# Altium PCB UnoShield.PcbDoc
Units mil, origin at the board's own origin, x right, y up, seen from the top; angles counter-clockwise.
Board outline 2700 x 2100 mil, 4 copper layers (Top Layer, Signal Layer 1, Signal Layer 2, Bottom Layer), stack 30.634 mil thick; 52 components, 29 nets, 160 pads, 29 vias.
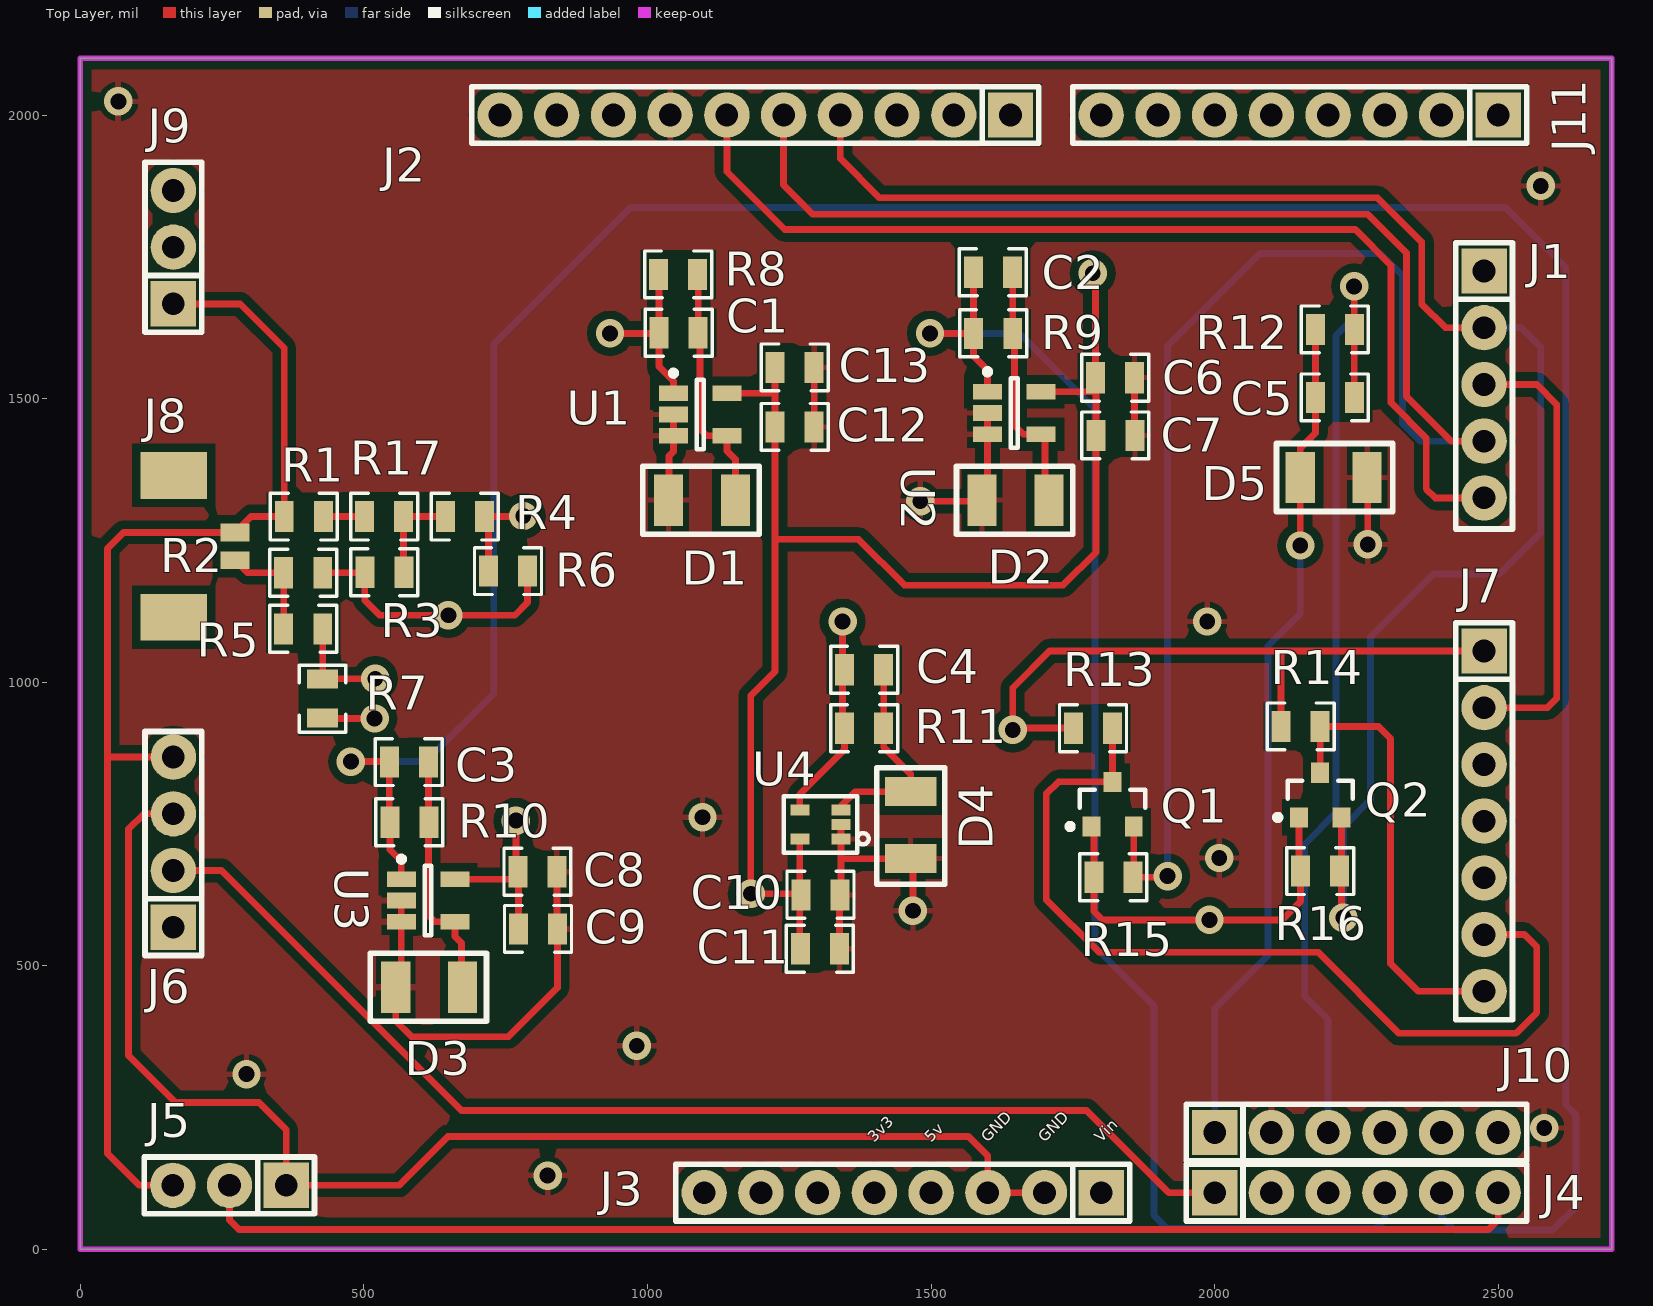
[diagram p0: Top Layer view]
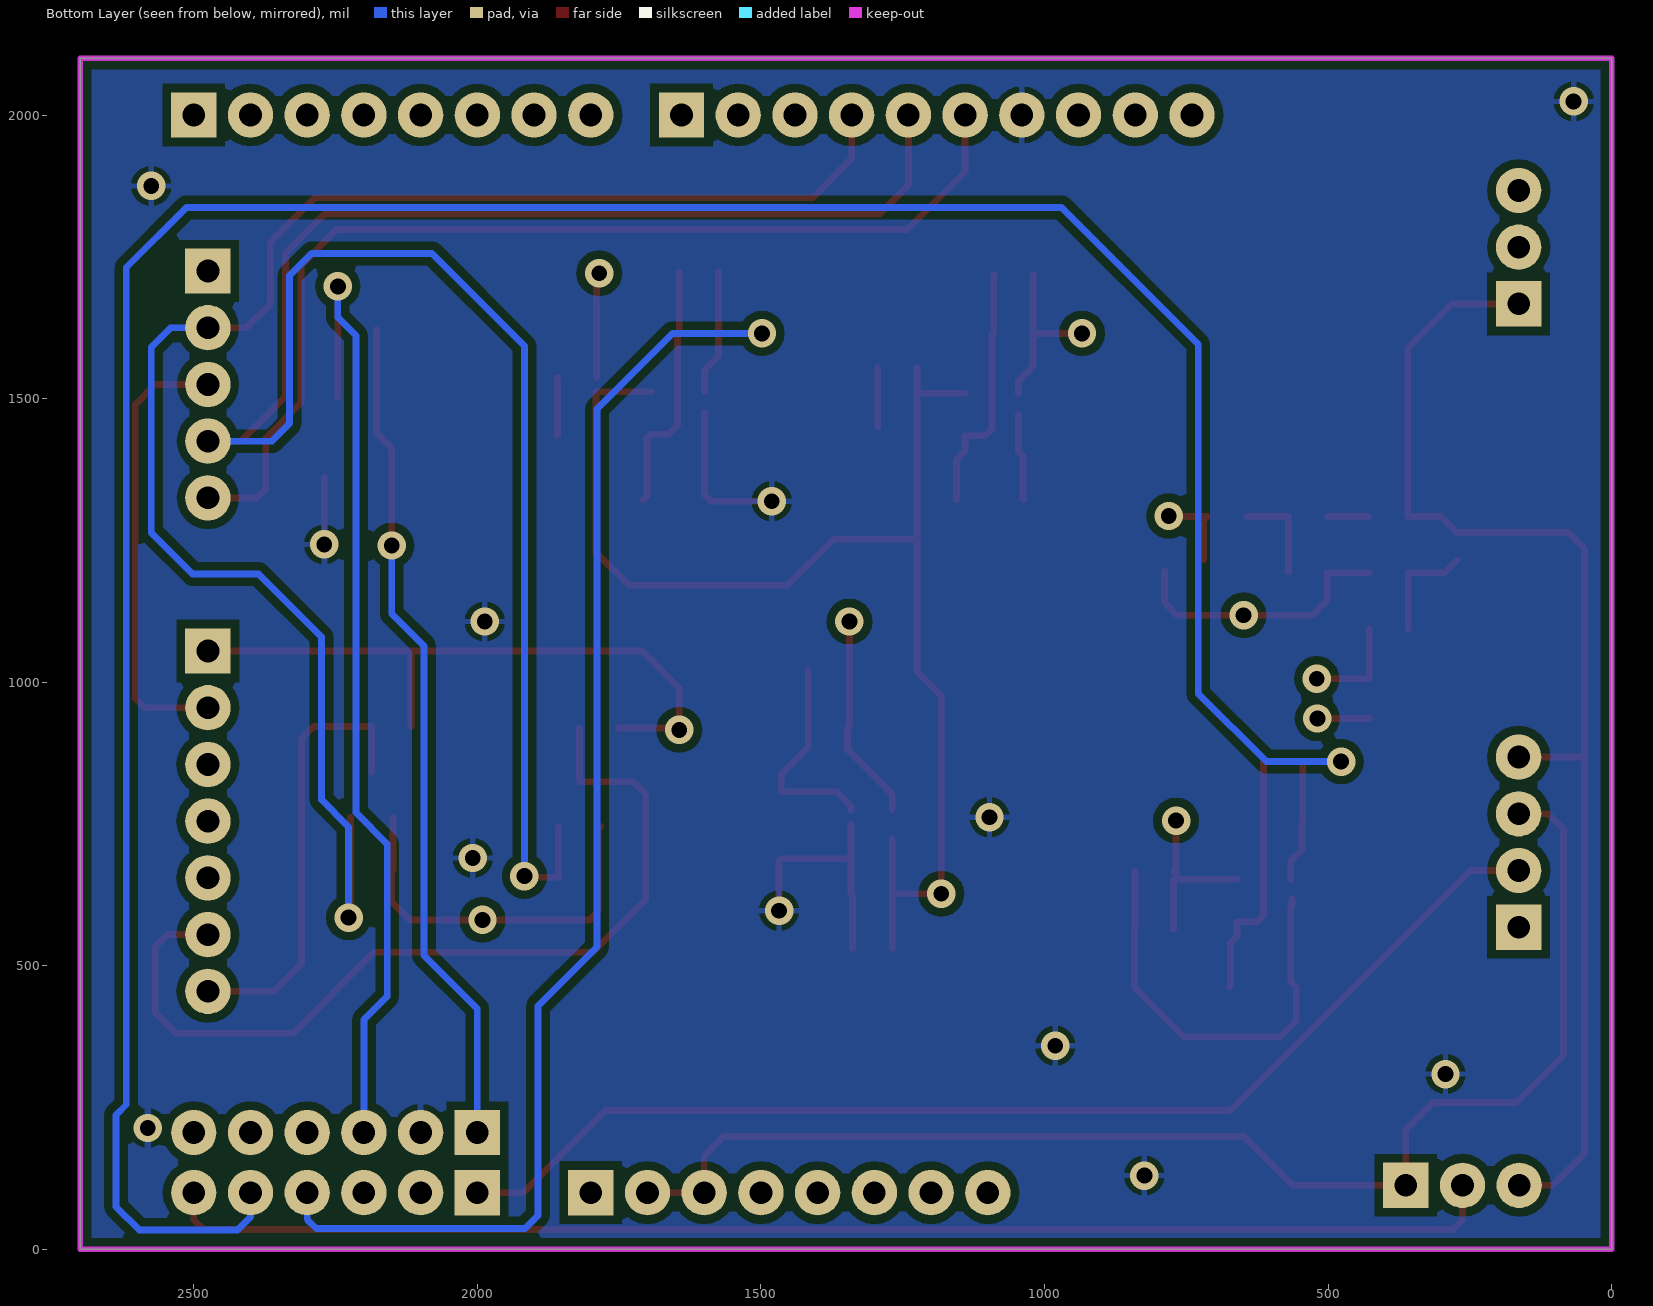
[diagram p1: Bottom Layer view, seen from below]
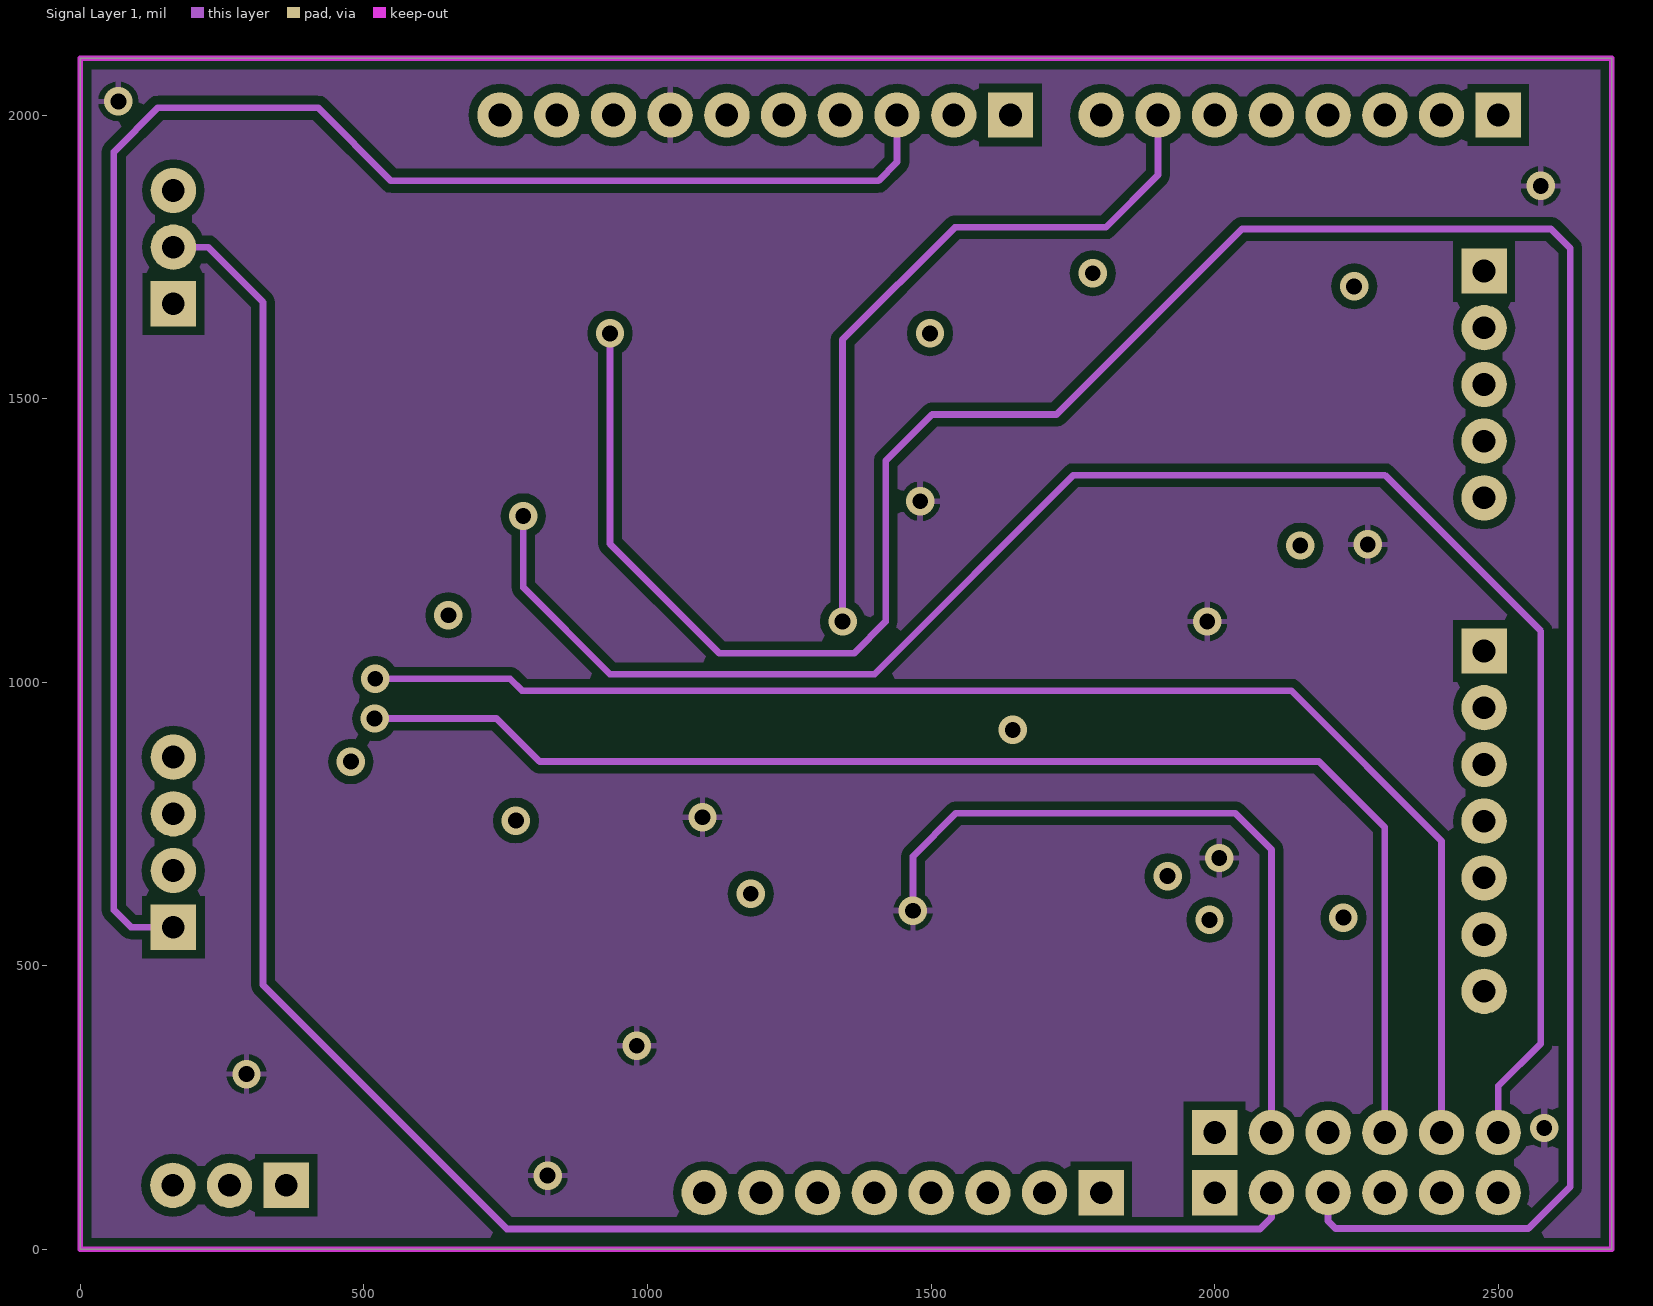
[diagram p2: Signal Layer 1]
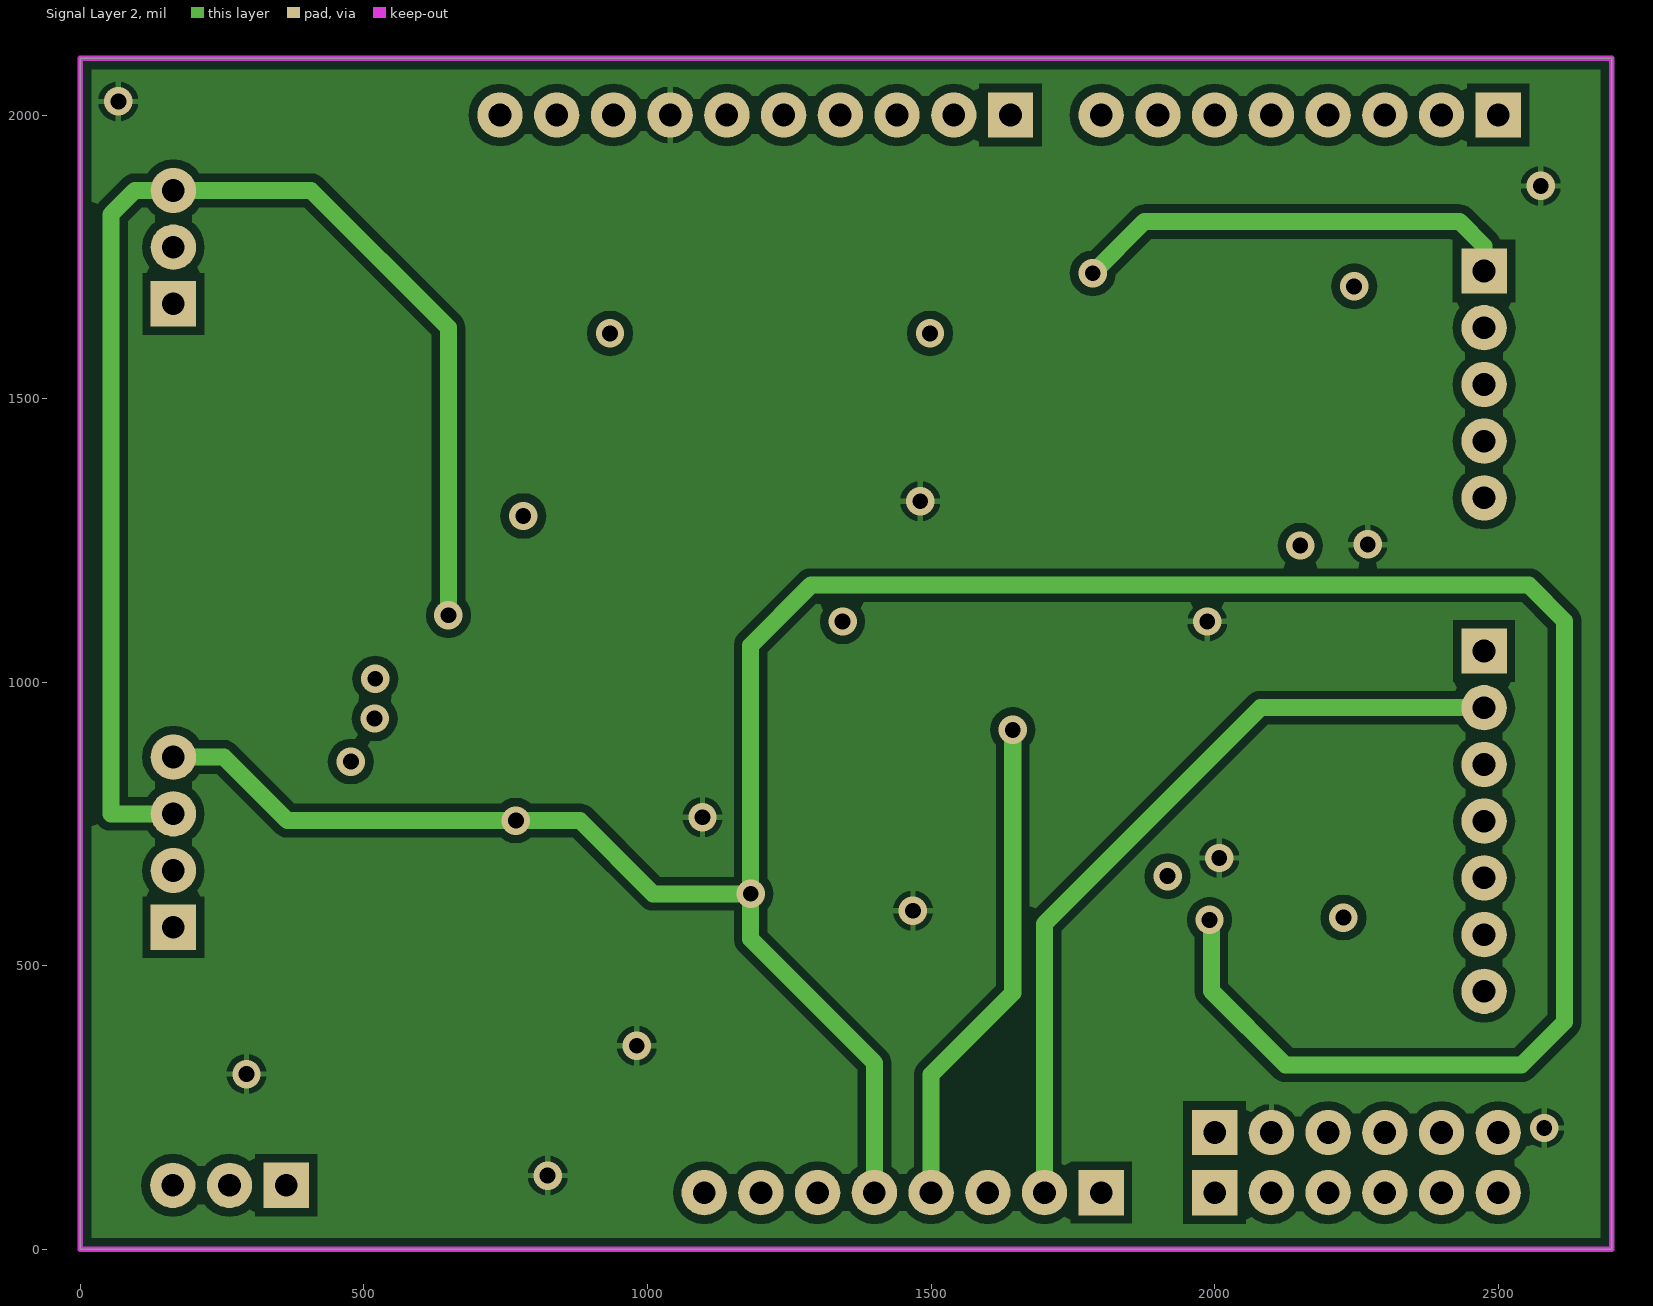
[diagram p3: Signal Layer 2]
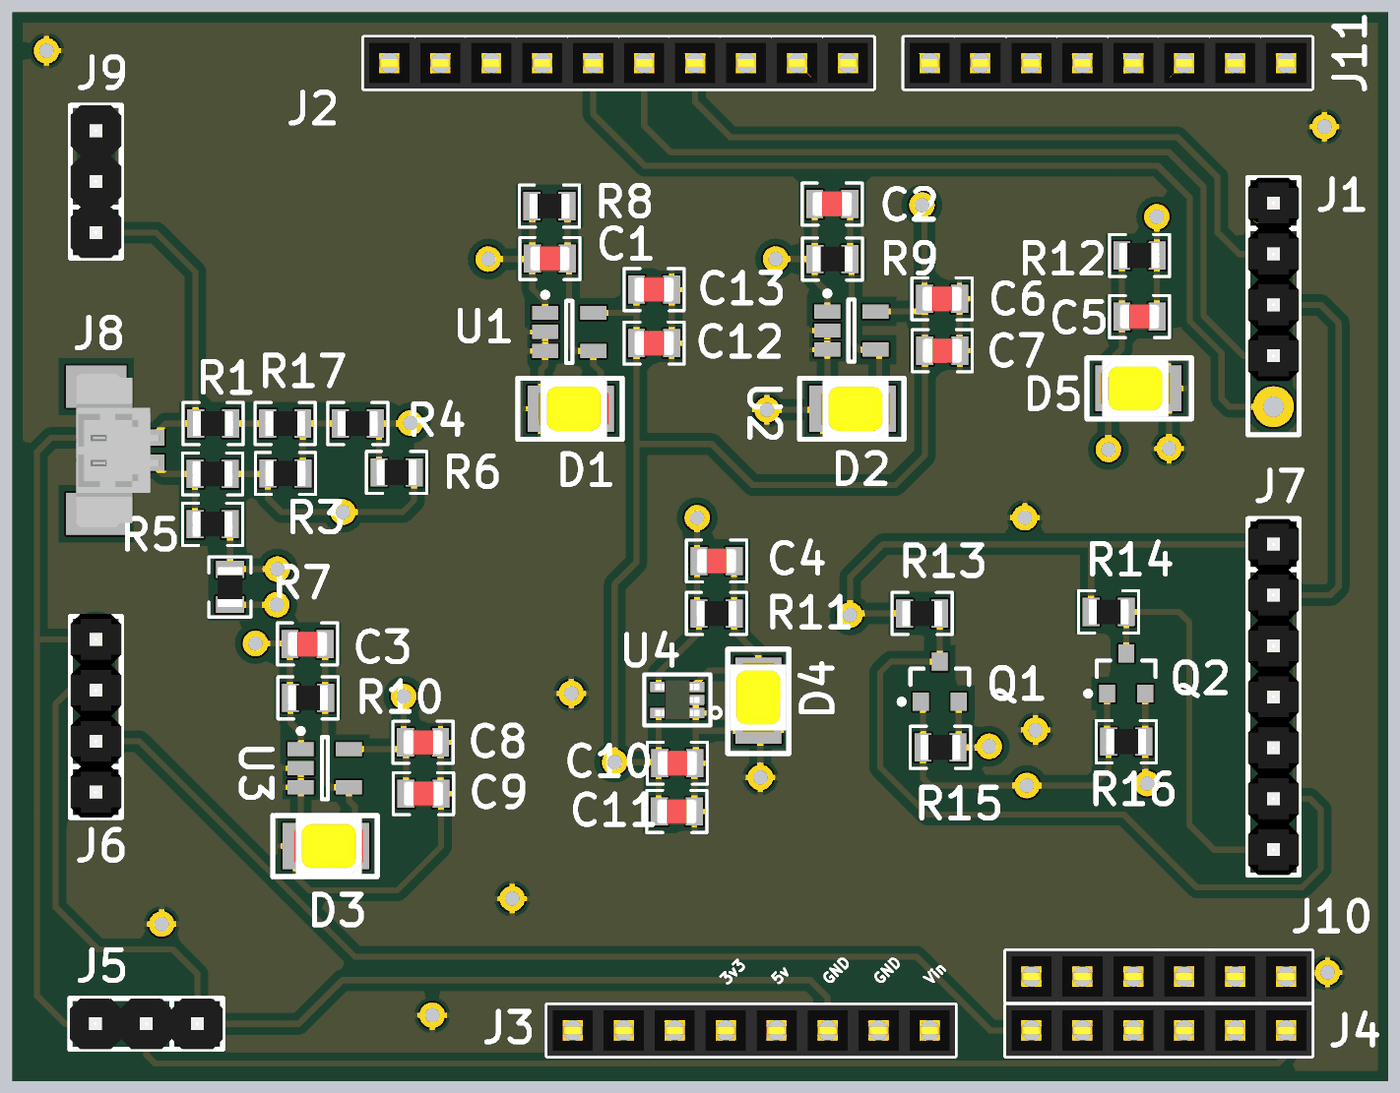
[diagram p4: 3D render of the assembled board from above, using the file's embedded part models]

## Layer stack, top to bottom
Top Solder: solder mask 0.4, Solder Resist, Dk 3.5
Top Layer: signal copper 1.4
Dielectric1: core 10, FR-4, Dk 4.2
Signal Layer 1: signal copper 1.417
Dielectric 3: prepreg 5, Dk 4.2
Signal Layer 2: signal copper 1.417
Dielectric 2: core 10, Dk 4.2
Bottom Layer: signal copper 1.4
Bottom Solder: solder mask 0.4, Solder Resist, Dk 3.5

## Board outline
0,0 0,2100 2700,2100 2700,1500 2700,0

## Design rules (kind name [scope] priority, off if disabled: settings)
Clearance [All] p1: gap=15 ignorepadtopadclearanceinfootprint=FALSE except(6: Arc-THPad Track-THPad)
ComponentClearance [All] p1: gap=5 collisioncheckmode=3 verticalgap=5 showdistances=FALSE
HoleSize [All] p1: absolutevalues=TRUE maxlimit=130 minlimit=1 maxpercent=80.000 minpercent=20.000
PolygonConnect [All] p1: connectstyle=Relief reliefconductorwidth=10 reliefentries=4 polygonreliefangle="90 Angle" airgapwidth=10
RoutingVias [All] p1: holewidth=15 width=30 viastyle="Through Hole" minholewidth=15 minwidth=30 maxholewidth=28 maxwidth=50
SilkToSolderMaskClearance SilkscreenOverComponentPads [IsPad] p1: minsilkscreentomaskgap=10 clearancetoexposedcopper=TRUE
SolderMaskExpansion [All] p1: expansion=4
Width [All] p1: maxlimit=50 minlimit=8 preferedwidth=12
27 further rules are at their usual default settings.

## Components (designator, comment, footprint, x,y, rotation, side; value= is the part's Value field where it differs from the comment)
C1 "10pF" CAP-0805(2012)-R 1055,1616 r180 top
C2 "10pF" CAP-0805(2012)-R 1609,1723 r180 top
C3 "10pF" CAP-0805(2012)-R 579.24,859.13 r180 top
C4 "10pF" CAP-0805(2012)-R 1382,1022 r180 top
C5 "Capacitance" CAP-0805(2012)-R 2212,1502 r0 top
C6 "100nF" CAP-0805(2012)-R 1824.45,1537 r0 top
C7 "1uF" CAP-0805(2012)-R 1825,1435 r0 top
C8 "100nF" CAP-0805(2012)-R 806,666 r0 top
C9 "1uF" CAP-0805(2012)-R 807,565 r0 top
C10 "100nF" CAP-0805(2012)-R 1305,625 r0 top
C11 "1uF" CAP-0805(2012)-R 1304,530 r0 top
C12 "100nF" CAP-0805(2012)-R 1259.45,1450 r0 top
C13 "1uF" CAP-0805(2012)-R 1259.45,1555 r0 top
D1 "GUVA-S12SD" "SMD 3528" 1036.89,1321 r270 top
D2 "GUVB-S11SD" "SMD 3528" 1589.89,1321 r270 top
D3 "GUVV-S10SD" "SMD 3528" 556.13,462.13 r270 top
D4 "GUVV-S10SD" "SMD 3528" 1464,688.89 r0 top
D5 "GUVA-S12SD" "SMD 3528" 2269,1361 r90 top
J1 "P1.X" "HEADER 8X1 8.5MM" 2500,2000 r180 top
J2 "P0.X" "HEADER 10X1 8.5MM" 1640,2000 r180 top
J3 "POWER_UNO" "HEADER 8X1 8.5MM" 1800,100 r180 top
J4 "P3.X" "HEADER 6X1 8.5MM" 2000,100 r0 top
J5 "GUVA-S12SD-B" "HEADER 3X1 8.5MM" 363,113 r180 top
J6 "ML8511" "HEADER 4X1 8.5MM" 164,568 r90 top
J7 "SI1145" "HEADER 7X1 8.5MM" 2475,1055 r270 top
J8 "Header 2 pin" WM7606CT-ND 273,1264.21 r270 top
J9 "LMT70-B" "HEADER 3X1 8.5MM" 164,1667 r90 top
J10 "P2.X" "HEADER 6X1 8.5MM" 2000,206 r0 top
J11 "TMP116EVM" "Header 5x1 8.5mm" 2475,1725 r270 top
Q1 "BSS138LT3G" ONSC-SOT-23-3-318-08_V 1820,785 r90 top
Q2 "BSS138LT3G" ONSC-SOT-23-3-318-08_V 2186,801 r90 top
R1 "Resistance" R-0805(2012)-R 394,1292 r0 top
R2 "Resistance" R-0805(2012)-R 393,1193 r0 top
R3 "Resistance" R-0805(2012)-R 536,1194 r180 top
R4 "Resistance" R-0805(2012)-R 678,1292 r0 top
R5 "Resistance" R-0805(2012)-R 393,1094 r0 top
R6 "Resistance" R-0805(2012)-R 754,1196 r180 top
R7 "Resistance" R-0805(2012)-R 427,971 r270 top
R8 "Resistance" R-0805(2012)-R 1054,1719 r180 top
R9 "Resistance" R-0805(2012)-R 1609.55,1615 r180 top
R10 "Resistance" R-0805(2012)-R 580.24,753.13 r180 top
R11 "Resistance" R-0805(2012)-R 1382,919 r180 top
R12 "Resistance" R-0805(2012)-R 2212,1622 r0 top
R13 "10K" R-0805(2012)-R 1785.55,919 r0 top
R14 "10K" R-0805(2012)-R 2151.55,922 r0 top
R15 "10K" R-0805(2012)-R 1821.45,656 r0 top
R16 "10K" R-0805(2012)-R 2186,667 r0 top
R17 "Resistance" R-0805(2012)-R 535.55,1292 r0 top
U1 "AD8538" SOT23-5 1093,1472 r0 top
U2 "AD8615" SOT23-5 1646.76,1474.6 r0 top
U3 "OPA336" SOT23-5 613.24,615.13 r0 top
U4 "OA1MPA" SC70-5L 1305,749 r180 top

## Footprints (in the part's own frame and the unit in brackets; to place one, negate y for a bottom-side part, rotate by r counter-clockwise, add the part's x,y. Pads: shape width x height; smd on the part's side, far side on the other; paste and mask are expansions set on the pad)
CAP-0805(2012)-R [mm] "Capacitor 0805(2012) Reflow"
  rect 0.85x1.4 smd: 1(-0.875,0) 2(0.875,0)
  silkscreen extent -1.5,-1.05 1.5,1.05, body extent -1,-0.63 1,0.63, height 0.78
"HEADER 3X1 8.5MM" [mil] "Stackable 3 pin header"
  rect 80x80 hole 40: 1(0,0)
  round 80 hole 40: 2(100,0) 3(200,0)
  silkscreen extent -50,-50 250,50, body extent -50,-50 250,50, height 350
"HEADER 4X1 8.5MM" [mil] "Stackable 4 pin header"
  rect 80x80 hole 40: 1(0,0)
  round 80 hole 40: 2(100,0) 3(200,0) 4(300,0)
  silkscreen extent -50,-50 345,50, body extent -50,-50 350,50, height 200
"Header 5x1 8.5mm" [mil] "Stackable 5 pin header"
  rect 80x80 hole 40: 1(0,0)
  round 80 hole 40: 2(100,0) 3(200,0) 4(300,0) 5(400,0)
  silkscreen extent -50,-50 455,50, body extent -50,-50 350,50, height 200
"HEADER 6X1 8.5MM" [mil] "Stackable 6 pin header"
  rect 80x80 hole 40: 1(0,0)
  round 80 hole 40: 2(100,0) 3(200,0) 4(300,0) 5(400,0) 6(500,0)
  silkscreen extent -50,-50 550,50, body extent -50,-50 550,50, height 335
"HEADER 7X1 8.5MM" [mil] "Stackable 7 pin header"
  rect 80x80 hole 40: 1(0,0)
  round 80 hole 40: 2(100,0) 3(200,0) 4(300,0) 5(400,0) 6(500,0) 7(600,0)
  silkscreen extent -50,-50 650,50, body extent -50,-50 650,50, height 200
"HEADER 8X1 8.5MM" [mil] "Stackable 8 pin header"
  rect 80x80 hole 40: 1(0,0)
  round 80 hole 40: 2(100,0) 3(200,0) 4(300,0) 5(400,0) 6(500,0) 7(600,0) 8(700,0)
  silkscreen extent -50,-50 750,50, body extent -50,-50 750,50, height 335
"HEADER 10X1 8.5MM" [mil] "Stackable 10 pin header"
  rect 80x80 hole 40: 1(0,0)
  round 80 hole 40: 2(100,0) 3(200,0) 4(300,0) 5(400,0) 6(500,0) 7(600,0) 8(700,0) 9(800,0) 10(900,0)
  silkscreen extent -50,-50 950,50, body extent -50,-50 950,50, height 335
ONSC-SOT-23-3-318-08_V [mm] "SOT23, 3-Leads, Body 2.92x1.3mm, Pitch 0.95mm"
  rect 0.9x0.8 smd: 1(-1,0.95) 2(-1,-0.95) 3(1,0)
  silkscreen extent -1.12,-1.46 0.65,2.02, body extent -0.65,-1.46 0.65,1.46, height 1.11
R-0805(2012)-R [mm] "Resistor 0805(2012) Reflow"
  rect 0.85x1.4 smd: 1(-0.875,0) 2(0.875,0)
  silkscreen extent -1.5,-1.05 1.5,1.05, body extent -1,-0.62 1,0.63, height 0.5
SC70-5L [mm] "SC70, 5-Leads, Body 2.20x2.7mm, Pitch 0.65mm"
  rect 0.85x0.5 smd: 1(-0.925,0.65) 2(-0.925,0) 3(-0.925,-0.65) 4(0.925,-0.65) 5(0.925,0.65)
  silkscreen extent -2.16,-1.27 1.65,1.27, body extent -1.1,-1 1.1,1, height 1
"SMD 3528" [mm]
  rect 2.3x1.3 smd: A(0,0) K(0,3)
  silkscreen extent -1.52,-1.14 1.52,4.06, body extent -1.4,-0.1 1.4,3.4, height 0.95
SOT23-5 [mm] "SOT23, 5-Leads, Body 2.9x1.7mm, Pitch 0.95mm, Lead Span 2.8mm, IPC Low Density"
  rect 1.3x0.7 smd: 1(-1.2,0.95) 2(-1.2,0) 3(-1.2,-0.95) 4(1.2,-0.95) 5(1.2,0.95)
  silkscreen extent -1.32,-1.55 0.15,1.97, body extent -0.9,-1.55 0.9,1.55, height 1.45
WM7606CT-ND [mm]
  rect 2.1x3 smd: 0(-2.55,-2.75) 0(3.8,-2.75)
  rect 0.8x1.3 smd: 1(0,0) 2(1.25,0)
  body extent -3.19,-3.76 4.46,0.44, height 4.72

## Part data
C1 C2 C3 C4: library part C-0805(2012), "___ OHM ___ mW 0805(2012) SMD", Case/Package=0805, Case Code (Metric)=2012, Dielectric=C0G, Dielectric Material=Ceramic, Manufacturer=Kemet, Manufacturer Part Number=C0805C100J5GAC-TU, Max Operating Temperature=125°C, Min Operating Temperature=-55°C, Package Quantity=1, Supplier Part Number 1=80-C0805C100J5G, Temperature Coefficient=30ppm/°C, Tolerance=5%, Voltage=50V
C5: library part C-0805(2012), "___ OHM ___ mW 0805(2012) SMD"
C6 C8 C10 C12: library part C-0805(2012), "___ OHM ___ mW 0805(2012) SMD", Case/Package=0805, Case Code (Metric)=2012, Dielectric=X7R, Insulation Resistance=100GR, Manufacturer=Yageo, Manufacturer Part Number=CC0805KRX7R9BB104, Max Operating Temperature=125°C, Min Operating Temperature=-55°C, Package Quantity=1, Supplier Part Number 1=603-CC805KRX7R9BB104, Tolerance=10%, Voltage=50V
C7 C9 C11 C13: library part C-0805(2012), "___ OHM ___ mW 0805(2012) SMD", Case/Package=0805, Case Code (Metric)=2012, Dielectric=X7R, Manufacturer=Yageo, Manufacturer Part Number=CC0805KKX7R7BB105, Max Operating Temperature=125°C, Min Operating Temperature=-55°C, Package Quantity=1, Supplier Part Number 1=603-CC805KKX7R7BB105, Tolerance=10%, Voltage Rating=16V
D1 D2 D3 D4 D5: "UV Photodiode, 3528 SMD"
J1: library part IOL
J2: library part IOH
J4: library part AD
J5 J6: "UV Light Sensor Breakout Board"
J7: "UV Light Sensor Digital"
J8: library part CON-2Pin, "Header, 2 pin, .1 pitch", Current Rating=-, Insulation Color=Natural, Manufacturer="Molex, LLC", Manufacturer Part Number=0533980271, Material Flammability Rating="UL94 V-0", Supplier Part Number 1=WM7606CT-ND
J9: "Precision Analog Temperature Sensor"
Q1 Q2: library part CMP-1058-00765-1, "Power MOSFET, 200 mA, 50 V, N-Channel, 3-Pin SOT-23, Pb-Free, Tape and Reel", Manufacturer="On Semiconductor", Package Type=SOT-23-3
R1 R2 R3 R4 R5 R6 R7 R8 R9 R10 R11 R12 R17: library part R-0805(2012), "___ OHM ___ mW 0805(2012) SMD"
R13 R14 R15 R16: library part R-0805(2012), "___ OHM ___ mW 0805(2012) SMD", Case/Package=0805, Case Code (Metric)=2012, Manufacturer=Yageo, Manufacturer Part Number=RC0805FR-0710KL, Max Operating Temperature=155°C, Max Power Dissipation=125mW, Min Operating Temperature=-55°C, Package Quantity=1, Supplier Part Number 1=603-RC0805FR-0710KL, Temperature Coefficient=100ppm/°C, Tolerance=1%, Voltage Rating=150V
U1: "IC SMD Atuo-Zero Op Amp Precision, Low Power", en - Input Voltage Noise Density="50 nV/sqrt Hz at 5 V", Ib - Input Bias Current="25 pA", Manufacturer="Analog Devices", Manufacturer Part Number=AD8538AUJZ-REEL7, Maximum Dual Supply Voltage="+/- 2.5 V", Maximum Operating Temperature="+ 125 C", Minimum Dual Supply Voltage="+/- 1.35 V", Minimum Operating Temperature="- 40 C", Operating Supply Current="180 uA", Operating Supply Voltage="2.7 V to 5.5 V", Package / Case=TSOT-5, PSRR - Power Supply Rejection Ratio="125 dB", Supplier Part Number 1=584-AD8538AUJZ-R7, Supply Voltage - Max="5.5 V", Supply Voltage - Min="2.7 V", Voltage Gain dB="141 dB", Vos - Input Offset Voltage="5 uV"
U2: "IC SMD Transimpedance Op Amp Precision", en - Input Voltage Noise Density="10 nV/sqrt Hz at 5 V", Ib - Input Bias Current="550 pA", Input Voltage Range - Max="5 V", Manufacturer="Analog Devices", Manufacturer Part Number=AD8615AUJZ-REEL7, Maximum Operating Temperature="+ 125 C", Minimum Operating Temperature="- 40 C", Operating Supply Current="1.7 mA", Operating Supply Voltage="2.7 V to 5 V", Output Current per Channel="150 mA", Package / Case=TSOT-5, PSRR - Power Supply Rejection Ratio="90 dB", Supplier Part Number 1=584-AD8615AUJZ-R7, Supply Voltage - Min="2.7 V", Voltage Gain dB="123.52 dB", Vos - Input Offset Voltage="80 uV"
U3: en - Input Voltage Noise Density="40 nV/sqrt Hz", Ib - Input Bias Current="10 pA", In - Input Noise Current Density="30 fA/sqrt Hz", Manufacturer="Texas Instruments", Manufacturer Part Number=OPA336NA/3K, Maximum Operating Temperature="+ 85 C", Minimum Operating Temperature="- 40 C", Operating Supply Current="20 uA", Operating Supply Voltage="2.3 V to 5.5 V", Package / Case=SOT-23-5, PSRR - Power Supply Rejection Ratio="25 uV/V", Supplier Part Number 1=595-OPA336NA/3K, Supply Voltage - Max="5.5 V", Supply Voltage - Min="2.3 V", Voltage Gain dB="115 dB", Vos - Input Offset Voltage="0.125 mV"
U4: Case/Package=SC, Input Bias Current=1pA, Input Offset Voltage (Vos)=200uV, Manufacturer=STMicroelectronics, Manufacturer Part Number=OA1MPA22C, Max Operating Temperature=125°C, Min Operating Temperature=-40°C, Operating Supply Current=10uA, Output Current per Channel=56mA, Package Quantity=3000, Supplier Part Number 1=511-OA1MPA22C, Supply Voltage=5.5V

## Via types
v1: diameter 50, hole 28, Top Layer to Bottom Layer, 29 vias

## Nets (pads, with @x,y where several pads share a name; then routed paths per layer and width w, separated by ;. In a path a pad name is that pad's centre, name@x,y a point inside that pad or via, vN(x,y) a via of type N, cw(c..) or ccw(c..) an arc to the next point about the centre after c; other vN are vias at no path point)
3.3V: C6.1 C7.1 C8.1 C9.1 C10.1 C11.1 C12.1 C13.1 J3.5 J5.3 J6.4 J8.1 J9.1 J11.1 Q1.1 Q2.1 R1.1 R15.1 R16.1 U1.5 U2.5 U3.5 U4.5 | length 11684.9
  Top Layer w12: J5.3 104,113 48,169 48,868 ; J6.4 48,868 ; J9.1 282,1667 359.55,1589.45 R1.1 300.79,1292 J8.1 76.21,1264.21 48,1236 48,868 ; U3.5 C8.1@772.55,652.54 ; v1(768,756) C8.1@768,669.55 ; C8.1 C8.1@768,669.55 ; C9.1 C8.1@772.55,652.54 ; U1.5 1222.6,1509.4 ; C13.1 C12.1 1225,1252 ; C11.1@1268.58,530 C10.1@1268.58,625 ; U4.5 C10.1@1268.58,625 ; U2.5 1790.55,1512 1791,1511.55 1791,1229 1733,1171 1453,1171 1372,1252 1225,1252 ; Q1.1 1787,741.23 R15.1 1787,596 1802,581 v1(1991,581) 2119.1,581 2151.55,613.45 R16.1 2148.6,669.95 Q2.1 ; v1(1785,1721) 1790,1716 C6.1 ; C8.1@768,669.55 768,657.09 C8.1@772.55,652.54 ; 1225,1252 1225,1019 1182,976 v1(1182,627) 1264.58,627 1265.58,628 C10.1@1268.58,625
  Signal Layer 2 w30: J6.4 253,868 365,756 v1(768,756) 881,756 1010,627 v1(1182,627) ; J3.5 1400,329 1182,547 v1(1182,627) ; v1(1785,1721) 1876,1812 2432,1812 2475,1769 J11.1 ; v1(1991,581) 1994,578 1994,456 2125,325 2541,325 2617,401 2617,1108 2554,1171 1288,1171 1182,1065 v1(1182,627)
5V: J3.4 J7.1 R13.1 R14.1 | length 2049.3
  Top Layer w12: R13.1 1647,919 v1(1644,916) 1644,990 1709,1055 2118,1055 ; R14.1 2117.1,1054.1 2118,1055 ; J7.1 2118,1055
  Signal Layer 2 w30: J3.4 1500,308 1644,452 v1(1644,916)
A_GUVA: J4.6 J5.2 | length 2360.1
  Top Layer w12: J5.2 263,52 280,35 2483,35 2500,52 J4.6
A_ML8511: J4.1 J6.2 | length 2071.3
  Top Layer w12: J6.2 249,668 672,245 1774,245 1919,100 J4.1
A_TEMP: J4.2 J9.2 | length 3410.6
  Signal Layer 1 w12: J9.2 225,1767 322,1670 322,466 752,36 2080,36 2100,56 J4.2
ALERT: J2.6 J11.5 | length 1867.7
  Top Layer w12: J2.6 1140,1900 1242,1798 2248,1798 2311,1735 2311,1492.82 2373,1430.82 2373,1341 2389,1325 J11.5
EN_ML8511: J2.3 J6.1 | length 3017.8
  Signal Layer 1 w12: J6.1 89,568 59,598 59,1935 137,2013 419,2013 548,1884 1407,1884 1440,1917 J2.3
GAIN: J10.4 R7.2 | length 2490.8
  Top Layer w12: R7.2 427.55,936 v1(519,936)
  Signal Layer 1 w12: v1(519,936) 734,936 810,860 2184,860 2300,744 J10.4
GND_1: J3.2 J3.3 J5.1 J6.3 J7.2 J9.3 J11.3 R2.2 R3.2 R6.1 | length 7447.5
  Top Layer w12: J6.3 112,768 85,741 85,342 168,259 315,259 363,211 J5.1 562,113 648,199 1566,199 1600,165 J3.3 J3.2 ; R2.2 500.55,1193 R3.2 501.55,1144.45 528,1118 v1(649,1118) 766,1118 788.45,1140.45 R6.1 ; J7.2 2587,955 2603,971 2603,1490 2568,1525 J11.3
  Signal Layer 2 w30: J6.3 54,768 54,1825 96,1867 J9.3 407,1867 649,1625 v1(649,1118) ; J3.2 1700,574 2081,955 J7.2
NetR1_2: R1.2 R17.1 | length 72.7
  Top Layer w12: R1.2 R17.1
SCL_3.3V: J2.5 J11.4 Q1.2 R15.2 | length 3696.1
  Top Layer w12: J2.5 1240,1877 1292,1825 2270,1825 2338,1757 2338,1504 2417,1425 J11.4 ; Q1.2 1857.4,657.5 R15.2 1915,656 v1(1917,658)
  Bottom Layer w12: v1(1917,658) 1917,1593 2080,1756 2292,1756 2331,1717 2331,1456 2362,1425 J11.4
SCL_5V: J7.6 Q1.3 R13.2 | length 1601.7
  Top Layer w12: R13.2 Q1.3 1724.37,824.37 1703,803 1703,617 1796,524 2182,524 2325,381 2531,381 2568,418 2568,533 2546,555 J7.6
SDA_3.3V: J2.4 J11.2 Q2.2 R16.2 | length 2909
  Top Layer w12: J2.4 1340,1923 1409,1854 2287,1854 2365,1776 2365,1667 2407,1625 J11.2 ; Q2.2 2223.4,588.6 v1(2227,585)
  Bottom Layer w12: v1(2227,585) 2227,744.82 2275,792.82 2275,1080 2386,1191 2502,1191 2575,1264 2575,1590 2540,1625 J11.2
SDA_5V: J7.7 Q2.3 R14.2 | length 796.6
  Top Layer w12: Q2.3 R14.2 2289,922 2310,901 2310,504 2359,455 J7.7
SG1: R3.1 R4.1 R17.2 | length 171.7
  Top Layer w12: R3.1 570,1194.45 R17.2 R4.1
SG1_A: J10.6 R4.2 R6.2 | length 3305.6
  Top Layer w12: R6.2@719.55,1216 719.55,1284.9 R4.2 780,1292 v1(781,1293)
  Signal Layer 1 w12: v1(781,1293) 781,1167 934,1014 1400,1014 1751,1365 2300,1365 2575,1090 2575,363 2500,288 J10.6
SG2: J8.2 R2.1 R5.1 | length 193.7
  Top Layer w12: J8.2 295,1193 R2.1 R5.1
SG2_A: J10.5 R5.2 R7.1 | length 2693.2
  Top Layer w12: R5.2 427.45,1005.9 427.55,1006 v1(520,1006)
  Signal Layer 1 w12: v1(520,1006) 758,1006 779,985 2135,985 2400,720 J10.5
UVD_1: C1.1 D1.K R8.1 U1.4 | length 446.6
  Top Layer w12: R8.1 1089.45,1718 C1.1 1092.35,1613.1 1092.35,1446.65 1104.4,1434.6 U1.4 1140.24,1407.76 1155,1393 D1.K
UVD_1A: C1.2 J4.3 R8.2 U1.1 | length 5109.7
  Top Layer w12: v1(934,1615) 1015.55,1615 1017.55,1613 C1.2 ; R8.2 1020.55,1718 C1.2 ; U1.1 1045.76,1531.24 1020.55,1556.45 C1.2
  Signal Layer 1 w12: v1(934,1615) 934,1244 1127,1051 1364,1051 1420,1107 1420,1390 1502,1472 1721,1472 2048,1799 2593,1799 2627,1765 2627,111 2553,37 2213,37 2200,50 J4.3
UVD_2: C2.1 D2.K R9.1 U2.4 | length 447
  Top Layer w12: C2.1 1644,1722.45 R9.1 1647,1612 1647,1453 1662.8,1437.2 U2.4 1701,1430.2 1701,1328 D2.K
UVD_2A: C2.2 J4.4 R9.2 U2.1 | length 2579.8
  Top Layer w12: v1(1498,1615) R9.2@1574.55,1615 ; C2.2 R9.2@1574.55,1615 ; R9.2 R9.2@1574.55,1615 ; U2.1 1599.51,1550.51 1574.55,1575.47 R9.2@1574.55,1615
  Bottom Layer w12: v1(1498,1615) 1656,1615 1789,1482 1789,533 1893,429 1893,60 1916,37 2284,37 2300,53 J4.4
UVD_3: C3.1 D3.K R10.1 U3.4 | length 443.1
  Top Layer w12: C3.1 613.69,588.69 624.65,577.73 U3.4 660.49,551.89 672.24,540.13 672.24,464.13 D3.K
UVD_3A: C3.2 J4.5 R10.2 U3.1 | length 5204.9
  Top Layer w12: v1(477,860) 543.93,860 C3.2 544.8,754.13 R10.2 545.8,704.58 566,684.38 U3.1
  Bottom Layer w12: v1(477,860) 609,860 729,980 729,1596 970,1837 2513,1837 2619,1731 2619,255 2637,237 2637,75 2596,34 2423,34 2400,57 J4.5
UVD_4: C4.1 D4.K R11.1 U4.3 | length 374.7
  Top Layer w12: U4.3 1341.42,781.42 1367,807 D4.K 1464,838 1416.45,885.55 R11.1 C4.1
UVD_4A: C4.2 J1.7 R11.2 U4.4 | length 1645.7
  Top Layer w12: U4.4 1268.58,802.58 1347.55,881.55 R11.2 1344,922.55 v1(1344,1107)
  Signal Layer 1 w12: v1(1344,1107) 1344,1604 1542,1802 1808,1802 1900,1894 J1.7
UVD_5GAIN: C5.2 J10.3 R12.2 | length 1741.2
  Top Layer w12: v1(2246,1698) 2246,1502.45 C5.2
  Bottom Layer w12: J10.3 2200,405 2159,446 2159,715 2214,770 2214,1611 2246,1643 v1(2246,1698)
UVD_5NEG: C5.1 D5.K J10.1 R12.1 | length 1489.5
  Top Layer w12: v1(2151,1241) 2151,1413 2177.55,1439.55 C5.1 R12.1
  Bottom Layer w12: J10.1 2000,424 2094,518 2094,1064 2151,1121 v1(2151,1241)
UVD_5POS: C6.2 C7.2 C8.2 C9.2 C10.2 C11.2 C12.2 C13.2 D1.A D2.A D3.A D4.A D5.A J2.7 J10.2 U1.2 U1.3 U2.2 U2.3 U3.2 U3.3 U4.1 U4.2 | length 3226.7
  Top Layer w12: U3.2@563.38,617.76 563.38,607 566,604.38 U3.3 566,472 D3.A 556.13,402.87 584,375 755,375 841.45,461.45 C9.2 840.45,566 C8.2 ; D1.A 1038,1322.11 1038,1399 1045.76,1406.76 U1.3 U1.2 ; C12.2 C13.2 ; C11.2 1338.45,624 C10.2 1341.42,626.97 1341.42,689 ; U4.2 U4.1 1341.42,689 ; v1(1468,597) 1468,684.89 D4.A 1341.53,688.89 1341.42,689 ; v1(1481,1319) 1587.89,1319 D2.A 1599.51,1330.62 U2.3 U2.2 ; C6.2 1858.9,1435.55 C7.2 ; D5.A 2270,1360 v1(2270,1243)
  Signal Layer 1 w12: v1(1468,597) 1468,693 1544,769 2036,769 2100,705 J10.2
  other v1: 824,130 2581,214 293,309 981,359 2008,690 1097,762 1987,1107 2575,1875 67,2024
pads on no net: J1.1 J1.2 J1.3 J1.4 J1.5 J1.6 J1.8 J2.1 J2.2 J2.8 J2.9 J2.10 J3.1 J3.6 J3.7 J3.8 J7.3 J7.4 J7.5 J8.0

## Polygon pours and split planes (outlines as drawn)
UVD_5POS on Signal Layer 2 "Signal_Layer_2_GND" (solid, remove dead copper, pour order 0): 20,20 2680,20 2680,2080 20,2080
UVD_5POS on Signal Layer 1 "Signal_Layer_1_GND" (solid, remove dead copper, pour order 2): 19.61,19.61 2679.61,19.61 2679.61,2079.61 19.61,2079.61
UVD_5POS on Bottom Layer "Bottom_Layer_GND" (solid, remove dead copper, pour order 4): 19.61,19.61 2679.61,19.61 2679.61,2079.61 19.61,2079.61
UVD_5POS on Top Layer "Top_Layer_GND" (solid, remove dead copper, pour order 6): 19.61,19.61 2679.61,19.61 2679.61,2079.61 19.61,2079.61

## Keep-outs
Keep-Out Layer:
  lines w10: 0,0 0,2100 2700,2100 2700,1499 2700,0 2600,0 0,0

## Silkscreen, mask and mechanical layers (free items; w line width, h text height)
Top Overlay:
  text "3v3" at 1400,187.07 h20 r45
  text "5v" at 1500,187.07 h20 r45
  text "GND" at 1600,187.07 h20 r45
  text "GND" at 1700,187.07 h20 r45
  text "Vin" at 1800,187.07 h20 r45
  text "RESET" at 1295,-2515 h20 r45
  text "3v3" at 1395,-2515 h20 r45
  text "5v" at 1495,-2515 h20 r45
  text "GND" at 1595,-2515 h20 r45
  text "GND" at 1695,-2515 h20 r45
  text "Vin" at 1795,-2515 h20 r45
Mechanical 1:
  circle w5: c600,2000 r62.99
Mechanical 3:
  lines w5: 0,0 2600,0 2700,0 2700,1500 2700,2100 0,2100 0,0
